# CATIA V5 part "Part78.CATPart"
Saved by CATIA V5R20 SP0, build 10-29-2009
Part number: IA 3075SF
Revision: ANY
Definition: UNKNOWN
Nomenclature: IA 3075SF
Source: Unknown
Bounding box of the stored display mesh (mm): x -1.5 to 1.5, y -2.85 to 4.9, z -1.5 to 1.5
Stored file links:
  C:\Users\Utente\Desktop\IO LAVORO\3D X SITO CF\CUMSA\3D files FA\FA 053004-21\Part78.CATPart

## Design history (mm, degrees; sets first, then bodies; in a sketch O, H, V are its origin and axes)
Body1 "Cortar-Extruir1" (main body)
  Solid1: solid without history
